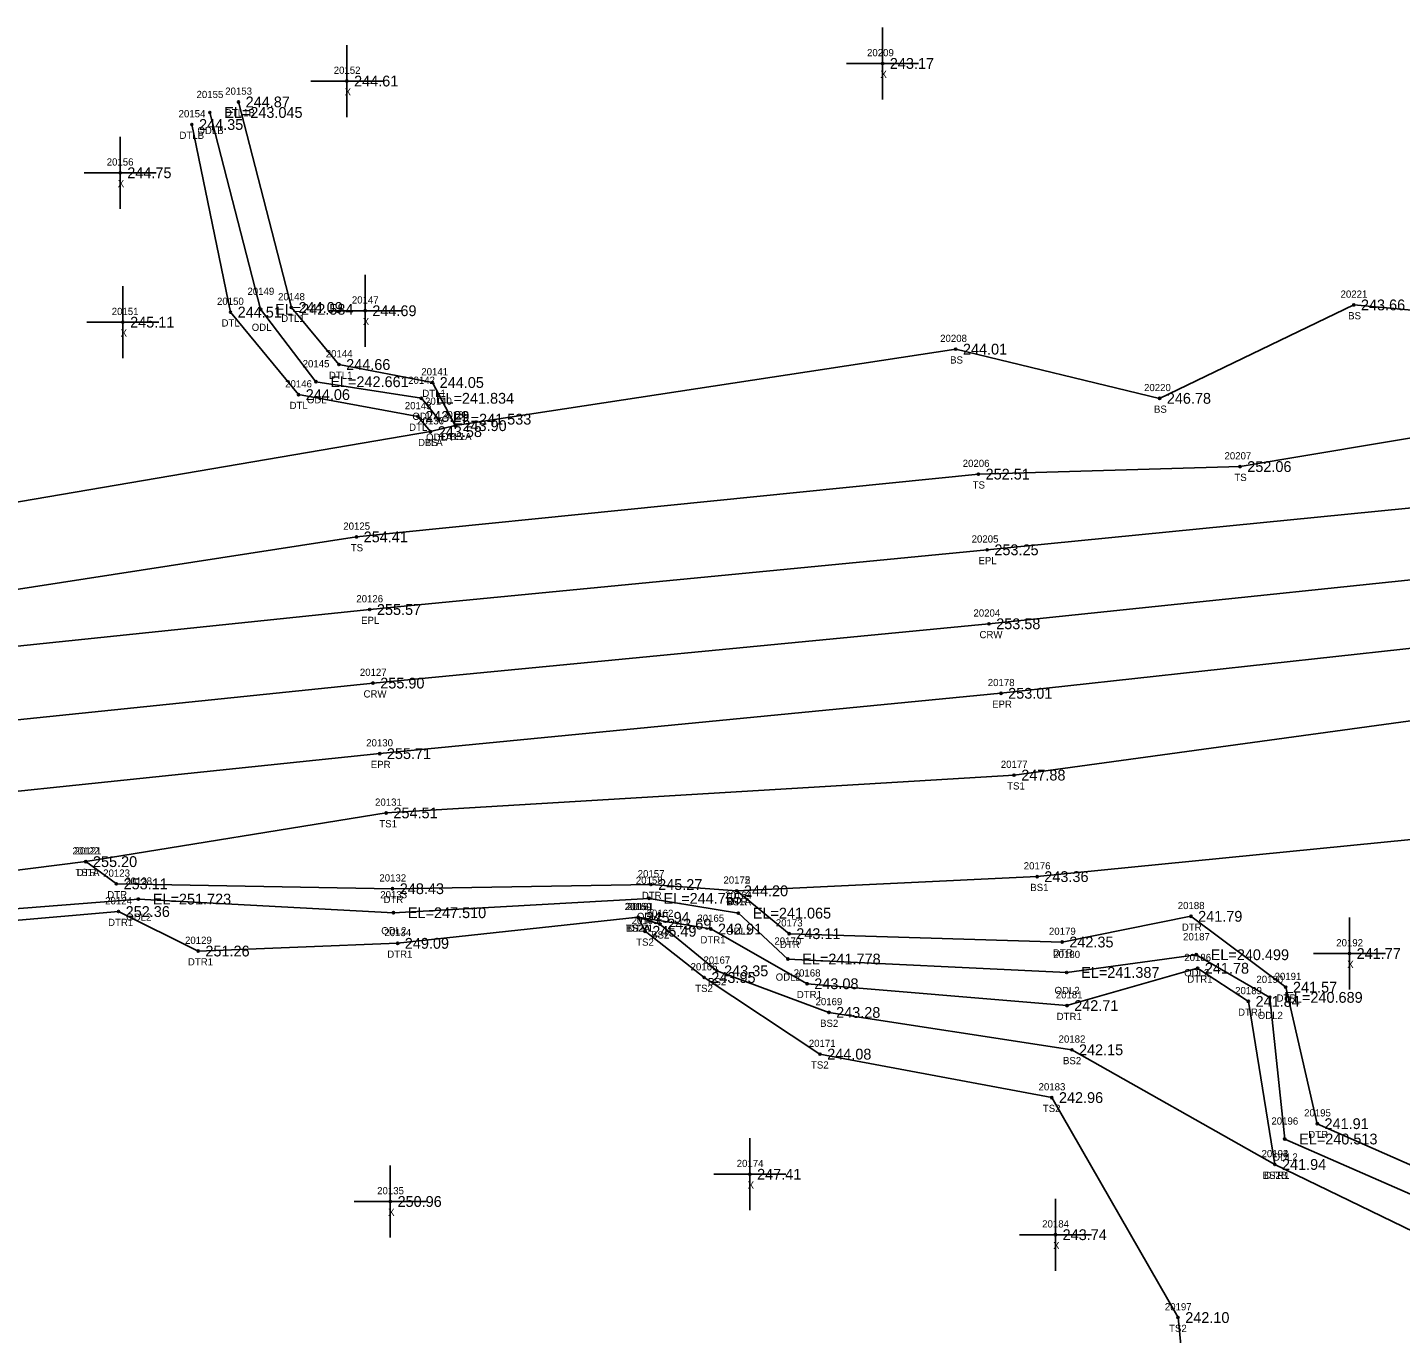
# Model space of a CAD drawing. Extents: x 2275563 to 2277161, y 1075719 to 1076412.
# Drawn here: x 2276101.9 to 2276292.5, y 1075959.9 to 1076141.2 of the extents above; entities that cross this region are included whole.
import ezdxf

# ---------------------------------------------------------------- set-up
doc = ezdxf.new("R2010")
doc.units = 0
for name, color, linetype in [('RD_DTM_BkLn1', 7, 'Continuous'), ('RD_DTM_BkLn2', 7, 'Continuous'), ('RD_DTM_BkLn_txCode', 7, 'Continuous'), ('RD_EX_H2O', 7, 'Continuous'), ('RD_EX_H2O_txCode', 7, 'Continuous'), ('RD_EX_Misc', 7, 'Continuous'), ('RD_EX_Misc_txCode', 7, 'Continuous'), ('RD_EX_Road', 7, 'Continuous'), ('RD_EX_Road_txCode', 7, 'Continuous'), ('RD_EX_TX_H2O_ELEV', 7, 'Continuous'), ('RD_EX_TX_Misc_ELEV', 7, 'Continuous'), ('RD_EX_TX_Road_ELEV', 7, 'Continuous'), ('RD_HC_Survey_ELEV', 7, 'Continuous'), ('RD_HC_Survey_txCode', 7, 'Continuous'), ('RD_SMD_Locator', 7, 'Continuous')]:
    doc.layers.add(name, color=color, linetype=linetype)

msp = doc.modelspace()

# ---------------------------------------------------------------- linework, layer by layer
at = {"layer": 'RD_DTM_BkLn1'}
msp.add_lwpolyline([(2275581.11, 1075960.98), (2275628.56, 1075975.85), (2275676.42, 1075988.42), (2275723.3, 1075998.64), (2275773.11, 1076007.87), (2275820.75, 1076014.85), (2275866.6, 1076020.4), (2275966.91, 1076031.19), (2276055.16, 1076040.4), (2276149.88, 1076050.18), (2276235.38, 1076058.41), (2276319.71, 1076067.21)], dxfattribs=at)
at = {"layer": 'RD_DTM_BkLn2'}
for points in [[(2275996.63, 1076057.66), (2276055.36, 1076067.63), (2276157.86, 1076085.08), (2276161.29, 1076085.91), (2276230.76, 1076096.53), (2276259.06, 1076089.7), (2276286.01, 1076102.67), (2276316.19, 1076099.9), (2276328.57, 1076094.65)], [(2276005.18, 1076050.59), (2276054, 1076055.99), (2276147.58, 1076070.47), (2276233.91, 1076079.18), (2276270.23, 1076080.23), (2276308.93, 1076086.72), (2276316.33, 1076084.42), (2276319.11, 1076080.29)], [(2276110, 1076025.4), (2276151.71, 1076032.16), (2276238.86, 1076037.41), (2276316.5, 1076048.03), (2276321.74, 1076054.53)], [(2276200.36, 1076021.35), (2276242.06, 1076023.32), (2276311.29, 1076030.17), (2276337.42, 1076033.52)], [(2276186.69, 1076017.67), (2276189.71, 1076016.73), (2276197.61, 1076010.24), (2276213.16, 1076004.47), (2276246.87, 1075999.28), (2276275.05, 1075983.37)], [(2276186.69, 1076017.67), (2276187.64, 1076015.73), (2276195.84, 1076009.31), (2276211.92, 1075998.68), (2276244.09, 1075992.65), (2276261.62, 1075962.12), (2276262.35, 1075955.07)]]:
    msp.add_lwpolyline(points, dxfattribs=at)
at = {"layer": 'RD_EX_H2O'}
for points in [[(2276161.29, 1076085.91), (2276158.13, 1076091.9), (2276145.15, 1076094.4), (2276138.54, 1076102.31), (2276131.2, 1076130.84)], [(2276158.97, 1076086.81), (2276156.59, 1076089.71), (2276141.95, 1076092.01), (2276134.28, 1076102.06), (2276127.22, 1076129.38)], [(2276157.86, 1076085.08), (2276156.12, 1076087.19), (2276139.54, 1076090.22), (2276130.09, 1076101.67), (2276124.73, 1076127.71)], [(2275584.42, 1075945.55), (2275630.75, 1075959.99), (2275679.72, 1075972.8), (2275727.1, 1075983.01), (2275776.52, 1075992.46), (2275822.09, 1075998.61), (2275868.31, 1076005.5), (2275971.07, 1076013.85), (2276058.03, 1076018.84), (2276110, 1076025.4), (2276114.25, 1076022.31), (2276152.59, 1076021.64), (2276188.46, 1076022.22), (2276200.36, 1076021.35), (2276207.63, 1076015.4), (2276245.53, 1076014.24), (2276263.41, 1076017.81), (2276276.57, 1076007.97), (2276280.95, 1075989.03), (2276329.97, 1075967.39)], [(2275584.66, 1075942.4), (2275631.99, 1075956.6), (2275680.23, 1075970.55), (2275727.34, 1075980.71), (2275776.9, 1075989.93), (2275822.49, 1075996.83), (2275868.2, 1076003.14), (2275971.77, 1076011.3), (2276058.74, 1076015.62), (2276117.31, 1076020.2), (2276152.71, 1076018.31), (2276188.2, 1076020.3), (2276200.59, 1076018.25), (2276207.46, 1076011.88), (2276246.17, 1076010.02), (2276264.15, 1076012.48), (2276274.37, 1076006.56), (2276276.43, 1075986.9), (2276334.04, 1075961.68)], [(2275587.87, 1075932.23), (2275632.3, 1075945.74), (2275680.34, 1075962.3), (2275730.43, 1075971.98), (2275777.84, 1075981.49), (2275823.91, 1075987.34), (2275869.26, 1075992.75), (2275941.88, 1076000), (2275968.29, 1076005.71), (2275973.41, 1076009.09), (2276058.49, 1076013.63), (2276114.54, 1076018.47), (2276125.61, 1076012.99), (2276153.29, 1076014.06), (2276186.69, 1076017.67), (2276196.76, 1076016.05), (2276210.13, 1076008.45), (2276246.2, 1076005.42), (2276264.34, 1076010.6), (2276271.38, 1076006), (2276275.05, 1075983.37), (2276331.39, 1075956.06)]]:
    msp.add_lwpolyline(points, dxfattribs=at)
at = {"layer": 'RD_EX_Misc'}
for p, q in [((2276220.61, 1076131.18), (2276220.61, 1076141.18)), ((2276146.25, 1076128.74), (2276146.25, 1076138.74)), ((2276215.61, 1076136.18), (2276225.61, 1076136.18)), ((2276141.25, 1076133.74), (2276151.25, 1076133.74)), ((2276114.77, 1076116.01), (2276114.77, 1076126.01)), ((2276109.77, 1076121.01), (2276119.77, 1076121.01)), ((2276148.78, 1076096.86), (2276148.78, 1076106.86)), ((2276115.16, 1076095.27), (2276115.16, 1076105.27)), ((2276143.78, 1076101.86), (2276153.78, 1076101.86)), ((2276110.16, 1076100.27), (2276120.16, 1076100.27)), ((2276285.41, 1076007.64), (2276285.41, 1076017.64)), ((2276280.41, 1076012.64), (2276290.41, 1076012.64)), ((2276202.19, 1075977.01), (2276202.19, 1075987.01)), ((2276152.28, 1075973.23), (2276152.28, 1075983.23)), ((2276197.19, 1075982.01), (2276207.19, 1075982.01)), ((2276147.28, 1075978.23), (2276157.28, 1075978.23)), ((2276244.6, 1075968.62), (2276244.6, 1075978.62)), ((2276239.6, 1075973.62), (2276249.6, 1075973.62))]:
    msp.add_line(p, q, dxfattribs=at)
at = {"layer": 'RD_EX_Road'}
for points in [[(2275577.73, 1075970.55), (2275625.95, 1075985.49), (2275674.01, 1075998.04), (2275722.5, 1076008.98), (2275771.65, 1076017.82), (2275820.48, 1076025.1), (2275865.7, 1076030.61), (2275949.17, 1076039.36), (2275965.19, 1076041.07), (2276054.28, 1076050.49), (2276149.42, 1076060.39), (2276235.13, 1076068.68), (2276318.87, 1076076.96)], [(2275583.24, 1075951.04), (2275629.66, 1075965.93), (2275678.06, 1075978.68), (2275725.56, 1075989.06), (2275775.66, 1075998.23), (2275820.79, 1076005.15), (2275867.87, 1076010.76), (2275970.82, 1076021.78), (2276056.64, 1076030.61), (2276150.8, 1076040.39), (2276237.04, 1076048.76), (2276320.71, 1076057.95)]]:
    msp.add_lwpolyline(points, dxfattribs=at)
at = {"layer": 'RD_SMD_Locator'}
for centre in [(2276220.61, 1076136.18), (2276146.25, 1076133.74), (2276131.2, 1076130.84), (2276127.22, 1076129.38), (2276124.73, 1076127.71), (2276114.77, 1076121.01), (2276130.09, 1076101.67), (2276134.28, 1076102.06), (2276138.54, 1076102.31), (2276148.78, 1076101.86), (2276286.01, 1076102.67), (2276115.16, 1076100.27), (2276230.76, 1076096.53), (2276145.15, 1076094.4), (2276141.95, 1076092.01), (2276158.13, 1076091.9), (2276139.54, 1076090.22), (2276156.59, 1076089.71), (2276259.06, 1076089.7), (2276156.12, 1076087.19), (2276158.97, 1076086.81), (2276157.86, 1076085.08), (2276157.86, 1076085.08), (2276161.29, 1076085.91), (2276161.29, 1076085.91), (2276233.91, 1076079.18), (2276270.23, 1076080.23), (2276147.58, 1076070.47), (2276235.13, 1076068.68), (2276149.42, 1076060.39), (2276235.38, 1076058.41), (2276149.88, 1076050.18), (2276237.04, 1076048.76), (2276150.8, 1076040.39), (2276238.86, 1076037.41), (2276151.71, 1076032.16), (2276110, 1076025.4), (2276110, 1076025.4), (2276242.06, 1076023.32), (2276114.25, 1076022.31), (2276152.59, 1076021.64), (2276188.46, 1076022.22), (2276200.36, 1076021.35), (2276200.36, 1076021.35), (2276117.31, 1076020.2), (2276188.2, 1076020.3), (2276114.54, 1076018.47), (2276152.71, 1076018.31), (2276186.69, 1076017.67), (2276186.69, 1076017.67), (2276186.69, 1076017.67), (2276200.59, 1076018.25), (2276263.41, 1076017.81), (2276187.64, 1076015.73), (2276189.71, 1076016.73), (2276196.76, 1076016.05), (2276153.29, 1076014.06), (2276207.63, 1076015.4), (2276245.53, 1076014.24), (2276125.61, 1076012.99), (2276207.46, 1076011.88), (2276264.15, 1076012.48), (2276285.41, 1076012.64), (2276197.61, 1076010.24), (2276246.17, 1076010.02), (2276264.34, 1076010.6), (2276195.84, 1076009.31), (2276210.13, 1076008.45), (2276276.57, 1076007.97), (2276274.37, 1076006.56), (2276213.16, 1076004.47), (2276246.2, 1076005.42), (2276271.38, 1076006), (2276211.92, 1075998.68), (2276246.87, 1075999.28), (2276244.09, 1075992.65), (2276280.95, 1075989.03), (2276276.43, 1075986.9), (2276275.05, 1075983.37), (2276275.05, 1075983.37), (2276202.19, 1075982.01), (2276152.28, 1075978.23), (2276244.6, 1075973.62), (2276261.62, 1075962.12)]:
    msp.add_circle(centre, 0.15, dxfattribs=at)

# ---------------------------------------------------------------- texts
at = {"layer": 'RD_DTM_BkLn_txCode'}
for s, p in [('20221', (2276284.18, 1076103.67)), ('BS', (2276285.23, 1076100.67)), ('20208', (2276228.6, 1076097.53)), ('BS', (2276229.98, 1076094.53)), ('20220', (2276256.9, 1076090.7)), ('BS', (2276258.28, 1076087.7)), ('20136', (2276156, 1076086.08)), ('20138', (2276159.46, 1076086.91)), ('BS', (2276160.51, 1076083.91)), ('BS', (2276157.08, 1076083.08)), ('20206', (2276231.73, 1076080.18)), ('20207', (2276268.07, 1076081.23)), ('TS', (2276269.44, 1076078.23)), ('TS', (2276233.11, 1076077.18)), ('20125', (2276145.75, 1076071.47)), ('TS', (2276146.79, 1076068.47)), ('20177', (2276237.02, 1076038.41)), ('TS1', (2276237.9, 1076035.41)), ('20131', (2276150.16, 1076033.16)), ('TS1', (2276150.75, 1076030.16)), ('20122', (2276108.16, 1076026.4)), ('20176', (2276240.2, 1076024.32)), ('TS1A', (2276108.55, 1076023.4)), ('20175', (2276198.52, 1076022.35)), ('BS1', (2276241.11, 1076021.32)), ('20160', (2276184.8, 1076018.67)), ('20161', (2276185.12, 1076018.67)), ('BS1A', (2276198.92, 1076019.35)), ('20163', (2276185.78, 1076016.73)), ('20162', (2276187.85, 1076017.73)), ('TS2A', (2276184.96, 1076015.67)), ('BS2A', (2276184.98, 1076015.67)), ('BS2', (2276188.48, 1076014.73)), ('TS2', (2276186.4, 1076013.73)), ('20167', (2276195.75, 1076011.24)), ('20166', (2276193.96, 1076010.31)), ('TS2', (2276194.6, 1076007.31)), ('BS2', (2276196.38, 1076008.24)), ('20169', (2276211.3, 1076005.47)), ('BS2', (2276211.93, 1076002.47)), ('20171', (2276210.37, 1075999.68)), ('20182', (2276245.04, 1076000.28)), ('TS2', (2276210.67, 1075996.68)), ('BS2', (2276245.65, 1075997.28)), ('20183', (2276242.26, 1075993.65)), ('TS2', (2276242.85, 1075990.65)), ('20194', (2276273.21, 1075984.37)), ('BS2B', (2276273.35, 1075981.37)), ('20197', (2276259.79, 1075963.12)), ('TS2', (2276260.38, 1075960.12))]:
    msp.add_text(s, height=1, dxfattribs=at).set_placement(p)
at = {"layer": 'RD_EX_H2O_txCode'}
for s, p in [('20155', (2276125.38, 1076131.38)), ('20153', (2276129.36, 1076131.84)), ('20154', (2276122.89, 1076128.71)), ('DTL1B', (2276129.32, 1076128.84)), ('DTLB', (2276123.01, 1076125.71)), ('ODLB', (2276125.5, 1076126.38)), ('20150', (2276128.22, 1076102.67)), ('20149', (2276132.45, 1076104.06)), ('20148', (2276136.7, 1076103.31)), ('DTL', (2276128.85, 1076099.67)), ('ODL', (2276133.04, 1076099.06)), ('DTL1', (2276137.13, 1076100.31)), ('20144', (2276143.32, 1076095.4)), ('20145', (2276140.11, 1076094.01)), ('20141', (2276156.58, 1076092.9)), ('20146', (2276137.68, 1076091.22)), ('DTL1', (2276143.75, 1076092.4)), ('20142', (2276154.76, 1076091.71)), ('DTL1', (2276156.72, 1076089.9)), ('DTL', (2276138.3, 1076088.22)), ('ODL', (2276140.7, 1076089.01)), ('20143', (2276154.29, 1076088.19)), ('20140', (2276157.1, 1076088.81)), ('ODL', (2276155.35, 1076086.71)), ('20137', (2276156.02, 1076086.08)), ('20139', (2276159.46, 1076086.91)), ('DTL', (2276154.88, 1076085.19)), ('ODLA', (2276157.24, 1076083.81)), ('DTL1A', (2276159.39, 1076083.91)), ('DTLA', (2276156.13, 1076083.08)), ('20121', (2276108.45, 1076026.4)), ('DTR', (2276108.73, 1076023.4)), ('20123', (2276112.42, 1076023.31)), ('20132', (2276150.76, 1076022.64)), ('20157', (2276186.62, 1076023.22)), ('20172', (2276198.52, 1076022.35)), ('20128', (2276115.48, 1076022.2)), ('20158', (2276186.36, 1076022.3)), ('20124', (2276112.7, 1076019.47)), ('DTR', (2276112.99, 1076020.31)), ('20133', (2276150.88, 1076020.31)), ('DTR', (2276151.33, 1076019.64)), ('20159', (2276184.86, 1076018.67)), ('DTR', (2276187.19, 1076020.22)), ('20164', (2276198.74, 1076020.25)), ('DTR', (2276199.09, 1076019.35)), ('20188', (2276261.58, 1076018.81)), ('ODL2', (2276115.62, 1076017.2)), ('ODL2', (2276186.5, 1076017.3)), ('20165', (2276194.9, 1076017.05)), ('DTR1', (2276113.1, 1076016.47)), ('ODL2', (2276151.02, 1076015.31)), ('20134', (2276151.45, 1076015.06)), ('DTR1', (2276185.26, 1076015.67)), ('ODL2', (2276198.9, 1076015.25)), ('20173', (2276205.79, 1076016.4)), ('20179', (2276243.7, 1076015.24)), ('DTR', (2276262.15, 1076015.81)), ('20129', (2276123.78, 1076013.99)), ('DTR1', (2276195.32, 1076014.05)), ('20170', (2276205.59, 1076013.88)), ('DTR', (2276206.36, 1076013.4)), ('20187', (2276262.32, 1076014.48)), ('DTR1', (2276124.18, 1076010.99)), ('DTR1', (2276151.85, 1076012.06)), ('DTR', (2276244.26, 1076012.24)), ('20180', (2276244.3, 1076012.02)), ('20186', (2276262.49, 1076011.6)), ('20168', (2276208.27, 1076009.45)), ('ODL2', (2276262.46, 1076009.48)), ('ODL2', (2276205.77, 1076008.88)), ('DTR1', (2276262.91, 1076008.6)), ('20190', (2276272.5, 1076008.56)), ('20191', (2276275.02, 1076008.97)), ('DTR1', (2276208.7, 1076006.45)), ('ODL2', (2276244.48, 1076007.02)), ('20181', (2276244.65, 1076006.42)), ('20189', (2276269.55, 1076007)), ('DTR', (2276275.3, 1076005.97)), ('DTR1', (2276244.77, 1076003.42)), ('DTR1', (2276269.95, 1076004)), ('ODL2', (2276272.68, 1076003.56)), ('20195', (2276279.12, 1075990.03)), ('20196', (2276274.58, 1075988.9)), ('DTR', (2276279.69, 1075987.03)), ('20193', (2276273.21, 1075984.37)), ('ODL2', (2276274.74, 1075983.9)), ('DTR1', (2276273.61, 1075981.37))]:
    msp.add_text(s, height=1, dxfattribs=at).set_placement(p)
at = {"layer": 'RD_EX_Misc_txCode'}
for s, p in [('20209', (2276218.45, 1076137.18)), ('20152', (2276144.42, 1076134.74)), ('X', (2276220.3, 1076134.18)), ('X', (2276145.94, 1076131.74)), ('20156', (2276112.91, 1076122.01)), ('X', (2276114.45, 1076119.01)), ('20147', (2276146.94, 1076102.86)), ('20151', (2276113.61, 1076101.27)), ('X', (2276148.46, 1076099.86)), ('X', (2276114.84, 1076098.27)), ('20192', (2276283.58, 1076013.64)), ('X', (2276285.1, 1076010.64)), ('20174', (2276200.36, 1075983.01)), ('20135', (2276150.45, 1075979.23)), ('X', (2276201.88, 1075980.01)), ('X', (2276151.97, 1075976.23)), ('20184', (2276242.76, 1075974.62)), ('X', (2276244.28, 1075971.62))]:
    msp.add_text(s, height=1, dxfattribs=at).set_placement(p)
at = {"layer": 'RD_EX_Road_txCode'}
for s, p in [('20205', (2276232.97, 1076069.68)), ('EPL', (2276233.92, 1076066.68)), ('20126', (2276147.56, 1076061.39)), ('EPL', (2276148.22, 1076058.39)), ('20178', (2276235.21, 1076049.76)), ('EPR', (2276235.81, 1076046.76)), ('20130', (2276148.93, 1076041.39)), ('EPR', (2276149.57, 1076038.39))]:
    msp.add_text(s, height=1, dxfattribs=at).set_placement(p)
at = {"layer": 'RD_EX_TX_H2O_ELEV'}
for s, p in [('EL=243.045', (2276129.22, 1076128.63)), ('244.87', (2276132.2, 1076130.09)), ('244.35', (2276125.73, 1076126.96)), ('244.51', (2276131.09, 1076100.92)), ('EL=242.584', (2276136.28, 1076101.31)), ('244.09', (2276139.54, 1076101.56)), ('244.66', (2276146.15, 1076093.65)), ('EL=242.661', (2276143.95, 1076091.26)), ('244.05', (2276159.13, 1076091.15)), ('244.06', (2276140.54, 1076089.47)), ('EL=241.834', (2276158.59, 1076088.96)), ('243.29', (2276157.12, 1076086.44)), ('EL=241.533', (2276160.97, 1076086.06)), ('243.90', (2276162.29, 1076085.16)), ('243.58', (2276158.86, 1076084.33)), ('255.20', (2276111, 1076024.65)), ('253.11', (2276115.25, 1076021.56)), ('248.43', (2276153.59, 1076020.89)), ('245.27', (2276189.46, 1076021.47)), ('244.20', (2276201.36, 1076020.6)), ('EL=251.723', (2276119.31, 1076019.45)), ('EL=244.755', (2276190.2, 1076019.55)), ('252.36', (2276115.54, 1076017.72)), ('EL=247.510', (2276154.71, 1076017.56)), ('245.94', (2276187.69, 1076016.92)), ('EL=241.065', (2276202.59, 1076017.5)), ('241.79', (2276264.41, 1076017.06)), ('242.91', (2276197.76, 1076015.3)), ('243.11', (2276208.63, 1076014.65)), ('249.09', (2276154.29, 1076013.31)), ('242.35', (2276246.53, 1076013.49)), ('251.26', (2276126.61, 1076012.24)), ('EL=241.778', (2276209.46, 1076011.13)), ('EL=240.499', (2276266.15, 1076011.73)), ('EL=241.387', (2276248.17, 1076009.27)), ('241.78', (2276265.34, 1076009.85)), ('243.08', (2276211.13, 1076007.7)), ('241.57', (2276277.57, 1076007.22)), ('242.71', (2276247.2, 1076004.67)), ('241.84', (2276272.38, 1076005.25)), ('EL=240.689', (2276276.37, 1076005.81)), ('241.91', (2276281.95, 1075988.28)), ('EL=240.513', (2276278.43, 1075986.15)), ('241.94', (2276276.05, 1075982.62))]:
    msp.add_text(s, height=1.5, dxfattribs=at).set_placement(p)
at = {"layer": 'RD_EX_TX_Misc_ELEV'}
for s, p in [('243.17', (2276221.61, 1076135.43)), ('244.61', (2276147.25, 1076132.99)), ('244.75', (2276115.77, 1076120.26)), ('243.66', (2276287.01, 1076101.92)), ('244.69', (2276149.78, 1076101.11)), ('245.11', (2276116.16, 1076099.52)), ('244.01', (2276231.76, 1076095.78)), ('246.78', (2276260.06, 1076088.95)), ('243.90', (2276162.29, 1076085.16)), ('243.58', (2276158.86, 1076084.33)), ('252.06', (2276271.23, 1076079.48)), ('252.51', (2276234.91, 1076078.43)), ('254.41', (2276148.58, 1076069.72)), ('247.88', (2276239.86, 1076036.66)), ('254.51', (2276152.71, 1076031.41)), ('255.20', (2276111, 1076024.65)), ('243.36', (2276243.06, 1076022.57)), ('244.20', (2276201.36, 1076020.6)), ('245.94', (2276187.69, 1076016.92)), ('245.94', (2276187.69, 1076016.92)), ('245.49', (2276188.64, 1076014.98)), ('243.69', (2276190.71, 1076015.98)), ('241.77', (2276286.41, 1076011.89)), ('243.95', (2276196.84, 1076008.56)), ('243.35', (2276198.61, 1076009.49)), ('243.28', (2276214.16, 1076003.72)), ('244.08', (2276212.92, 1075997.93)), ('242.15', (2276247.87, 1075998.53)), ('242.96', (2276245.09, 1075991.9)), ('241.94', (2276276.05, 1075982.62)), ('247.41', (2276203.19, 1075981.26)), ('250.96', (2276153.28, 1075977.48)), ('243.74', (2276245.6, 1075972.87)), ('242.10', (2276262.62, 1075961.37))]:
    msp.add_text(s, height=1.5, dxfattribs=at).set_placement(p)
at = {"layer": 'RD_EX_TX_Road_ELEV'}
for s, p in [('253.25', (2276236.13, 1076067.93)), ('255.57', (2276150.42, 1076059.64)), ('253.01', (2276238.04, 1076048.01)), ('255.71', (2276151.8, 1076039.64))]:
    msp.add_text(s, height=1.5, dxfattribs=at).set_placement(p)
at = {"layer": 'RD_HC_Survey_ELEV'}
for s, p in [('253.58', (2276236.38, 1076057.66)), ('255.90', (2276150.88, 1076049.43))]:
    msp.add_text(s, height=1.5, dxfattribs=at).set_placement(p)
at = {"layer": 'RD_HC_Survey_txCode'}
for s, p in [('20204', (2276233.22, 1076059.41)), ('CRW', (2276234.06, 1076056.41)), ('20127', (2276148.05, 1076051.18)), ('CRW', (2276148.56, 1076048.18))]:
    msp.add_text(s, height=1, dxfattribs=at).set_placement(p)

doc.saveas('drawing.dxf')
